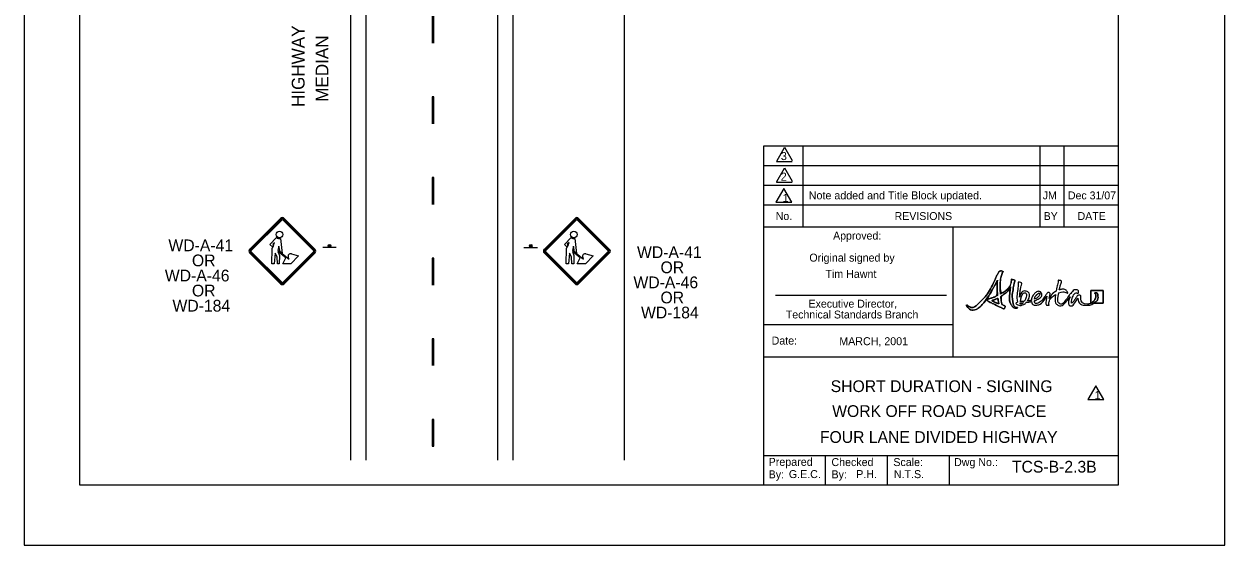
# Model space of a CAD drawing. Extents: x 1351 to 1567, y 178 to 457.
# Drawn here: x 1351.4 to 1567.4, y 177.9 to 271.7 of the extents above; entities that cross this region are included whole.
import ezdxf

# ---------------------------------------------------------------- set-up
doc = ezdxf.new("R2010")
doc.units = 0
for name, color, linetype in [('Level 1', 7, 'Continuous'), ('Level 10', 7, 'Continuous'), ('Level 2', 7, 'Continuous'), ('Level 22', 7, 'Continuous'), ('Level 44', 7, 'Continuous'), ('Level 45', 7, 'Continuous'), ('Level 53', 7, 'Continuous'), ('Level 60', 7, 'Continuous'), ('Level 63', 7, 'Continuous'), ('Level 7', 7, 'Continuous')]:
    doc.layers.add(name, color=color, linetype=linetype)

# ---------------------------------------------------------------- blocks, each defined once
blk = doc.blocks.new('ORIG')
at = {"layer": 'Level 2'}
blk.add_line((0, 0), (0, 0), dxfattribs=at)
at = {"layer": 'Level 7'}
for s, p in [('Original signed by', (-25.835, -6.257)), ('Tim Hawnt', (-22.945, -9.191))]:
    blk.add_text(s, height=1.434, dxfattribs=at).set_placement(p)
blk = doc.blocks.new('REVBK')
at = {"layer": 'Level 44'}
for p, q in [((63.873, 14.55), (-0.007, 14.55)), ((63.873, 11.001), (-0.007, 11.001)), ((63.873, 7.452), (-0.007, 7.452)), ((63.873, 3.904), (-0.007, 3.904)), ((0, 0), (63.873, 0))]:
    blk.add_line(p, q, dxfattribs=at)
blk.add_lwpolyline([(3.62, 6.885), (2.201, 4.415), (5.039, 4.415)], close=True, dxfattribs=at)
at = {"layer": 'Level 45'}
blk.add_line((34.066, 0), (34.066, 0), dxfattribs=at)
at = {"layer": 'Level 63'}
for p, q in [((0, 8.078), (0, 14.55)), ((7.09, 8.078), (7.09, 14.55)), ((49.679, 14.55), (49.679, 0)), ((53.99, 14.55), (53.99, 0)), ((0, 0), (0, 8.078)), ((7.09, 0), (7.09, 8.078))]:
    blk.add_line(p, q, dxfattribs=at)
for points in [[(3.699, 14.219), (2.306, 11.794)], [(5.181, 11.871), (3.787, 14.296)], [(2.306, 11.794), (2.28, 11.749), (5.119, 11.749), (5.093, 11.794)], [(3.699, 10.503), (2.306, 8.078)], [(5.181, 8.155), (3.787, 10.58)], [(2.306, 8.078), (2.28, 8.033), (5.119, 8.033), (5.093, 8.078)]]:
    blk.add_lwpolyline(points, dxfattribs=at)
at = {"layer": 'Level 44'}
for s, height, p in [('3', 1.448, (3.089, 12.018)), ('2', 1.448, (3.072, 8.302)), ('1', 1.448, (3.393, 4.472)), ('JM', 1.4189, (50.183, 4.953)), ('Dec 31/07', 1.419, (54.724, 4.953)), ('No.', 1.4195, (2.172, 1.235)), ('REVISIONS', 1.4195, (23.555, 1.235)), ('BY', 1.4194, (50.361, 1.235)), ('DATE', 1.4194, (56.463, 1.235))]:
    blk.add_text(s, height=height, rotation=360, dxfattribs=at).set_placement(p)
blk = doc.blocks.new('C_LINE')
at = {"layer": 'Level 2'}
for p, q in [((-0.145, 77.408), (-0.145, 72.57)), ((0.145, 72.57), (0.145, 77.408)), ((-0.145, 62.894), (-0.145, 58.056)), ((0.145, 62.894), (-0.145, 62.894)), ((0.145, 58.056), (0.145, 62.894)), ((-0.145, 48.38), (-0.145, 43.542)), ((0.145, 48.38), (-0.145, 48.38)), ((0.145, 43.542), (0.145, 48.38)), ((-0.145, 33.866), (-0.145, 29.028)), ((0.145, 33.866), (-0.145, 33.866)), ((0.145, 29.028), (0.145, 33.866)), ((-0.145, 19.352), (-0.145, 14.514)), ((0.145, 19.352), (-0.145, 19.352)), ((0.145, 14.514), (0.145, 19.352)), ((-0.145, 4.838), (-0.145, 0)), ((0.145, 4.838), (-0.145, 4.838)), ((0.145, 0), (0.145, 4.838)), ((-0.145, 0), (0.145, 0))]:
    blk.add_line(p, q, dxfattribs=at)
blk = doc.blocks.new('Alberta Signature')
at = {"layer": 'Level 53'}
blk.add_line((-5.9, -14.5), (-13.3, -14.5), dxfattribs=at)
blk.add_lwpolyline([(-5.9, -14.5), (15.6, -14.5), (15.6, 15.2), (-14.1, 15.2), (-14.1, -14.5), (-13.3, -14.5)], dxfattribs=at)
for points, degree in [([(-192.4, -25.3), (-195.6, -24.8), (-199.8, -20.5), (-201, -13.3), (-203.3, -0.4), (-202, 12.3), (-198.2, 31.2), (-197.5, 34.8), (-195, 41), (-202.8, 42.2), (-205.3, 42.6), (-204, 41.4), (-204.7, 38.1), (-207.7, 24), (-219.2, 13.8), (-230.8, 7), (-232, 23.2), (-231.5, 41.1), (-228.5, 52.1), (-225.9, 61.4), (-222.9, 59.7), (-226.7, 61.7), (-230.6, 63.7), (-234.9, 61), (-238.4, 54.1), (-241.8, 47.2), (-257.8, 9.6), (-283.3, -15.7), (-296.3, -28.7), (-308.1, -22), (-310.5, -20), (-312.4, -18.4), (-313.1, -20.9), (-310.7, -23.5), (-300.2, -34.8), (-284.8, -28.3), (-279.2, -22.7), (-263.7, -7.2), (-245.6, 26.2), (-238.3, 40.3), (-239, 32.3), (-239.2, 19), (-237.8, 3.3), (-245.7, -0.5), (-252.7, -2.8), (-256.1, -3.7), (-259.7, -4.6), (-261.9, -6.1), (-262, -7.8), (-262.1, -9.6), (-259.6, -11.2), (-256.1, -12.8), (-249.9, -15.8), (-231.6, -24.4), (-227.1, -27), (-223.2, -29.3), (-221.3, -27.5), (-220.2, -25.1), (-218.7, -22), (-222.8, -20.2), (-226.8, -19), (-228.3, -13.7), (-229.5, -6.5), (-230.3, 1.3), (-221, 7.1), (-211.9, 14.7), (-206.6, 24.2), (-207.9, 16.3), (-211.3, -10.8), (-202.8, -22.3), (-200.9, -24.8), (-196.7, -27.5), (-192.7, -27.1), (-190.8, -26.9), (-189.8, -25.7), (-190, -25.3), (-190.2, -24.9), (-191.3, -25.5), (-192.4, -25.3)], 3), ([(-230.8, 7), (-232, 23.2), (-231.5, 41.1), (-228.5, 52.1), (-225.9, 61.4), (-222.9, 59.7), (-226.7, 61.7), (-230.6, 63.7), (-234.9, 61), (-238.4, 54.1), (-241.8, 47.2), (-257.8, 9.6), (-283.3, -15.7), (-296.3, -28.7), (-308.1, -22), (-310.5, -20), (-312.4, -18.4), (-313.1, -20.9), (-310.7, -23.5), (-300.2, -34.8), (-284.8, -28.3), (-279.2, -22.7), (-263.7, -7.2), (-245.6, 26.2), (-238.3, 40.3)], 3), ([(-238.3, 40.3), (-239, 32.3), (-239.2, 19), (-237.8, 3.3)], 2), ([(-192.4, -25.3), (-195.6, -24.8), (-199.8, -20.5), (-201, -13.3), (-203.3, -0.4), (-202, 12.3), (-198.2, 31.2), (-197.5, 34.8), (-195, 41), (-202.8, 42.2), (-205.3, 42.6), (-204, 41.4), (-204.7, 38.1), (-207.7, 24), (-219.2, 13.8), (-230.8, 7)], 3), ([(-185.2, -0.7), (-184.6, 6.9), (-183.4, 16.1), (-181.7, 24.7), (-181, 28.2), (-178.5, 34.4), (-186.3, 35.6), (-188.8, 36), (-188.4, 34.9), (-188.2, 31.5), (-187.9, 27), (-192.9, -0.2), (-190.3, -12.1)], 3), ([(-89.8, 17.1), (-89, 21.1), (-88, 25.1), (-86.9, 29.1), (-85.9, 32.6), (-82.9, 38.9), (-90.6, 40), (-93.1, 40.4), (-92, 39.2), (-92.8, 35.9), (-94.3, 29.8), (-96.2, 21.9), (-97.5, 14)], 3), ([(-237.8, 3.3), (-245.7, -0.5), (-252.7, -2.8), (-256.1, -3.7), (-259.7, -4.6), (-261.9, -6.1), (-262, -7.8), (-262.1, -9.6), (-259.6, -11.2), (-256.1, -12.8), (-249.9, -15.8), (-231.6, -24.4), (-227.1, -27), (-223.2, -29.3), (-221.3, -27.5), (-220.2, -25.1), (-218.7, -22), (-222.8, -20.2), (-226.8, -19)], 3), ([(-230.3, 1.3), (-221, 7.1), (-211.9, 14.7), (-206.6, 24.2)], 2), ([(-226.8, -19), (-228.3, -13.7), (-229.5, -6.5), (-230.3, 1.3)], 2), ([(-206.6, 24.2), (-207.9, 16.3), (-211.3, -10.8), (-202.8, -22.3), (-200.9, -24.8), (-196.7, -27.5), (-192.7, -27.1), (-190.8, -26.9), (-189.8, -25.7), (-190, -25.3), (-190.2, -24.9), (-191.3, -25.5), (-192.4, -25.3)], 3), ([(-166.1, -9.6), (-160.5, -0.6), (-161, 11.5), (-169.1, 13.6), (-178.5, 16), (-183.2, 6.8), (-185.2, -0.7)], 3), ([(-183.2, -11.3), (-182, -1.7), (-177, 11.5), (-170.8, 9.4), (-167.3, 8.2), (-169.1, -3), (-173.7, -10.4)], 3), ([(-149.7, -9.2), (-148.4, -8.9), (-147.3, -8.5), (-146.3, -8), (-134.5, -2.8), (-130.5, 5.1), (-133.5, 9.9), (-136.3, 14.4), (-144.5, 13), (-150.9, 6.3), (-154, 2.9), (-156.5, -2.8), (-156.7, -8)], 3), ([(-156.6, -10.9), (-156, -16.2), (-152.6, -20.2), (-144.6, -19.4), (-133.4, -18.4), (-123.3, -4.5), (-119.6, 2.2)], 3), ([(-114.1, -3.7), (-113.3, 0), (-112.2, 4), (-112.1, 6.8), (-112, 9.7), (-114, 10.3), (-114.8, 10.6), (-116.4, 11), (-118.5, 10.2), (-120.5, 7.4), (-125.2, 0.7), (-131.2, -9.8), (-140.2, -14.2), (-146.7, -17.3), (-149.6, -14.1), (-149.7, -9.2)], 3), ([(-143.4, 5.7), (-139.5, 9.3), (-137.5, 9.1), (-137, 8.1), (-135.9, 6), (-140.5, -1.5), (-149.4, -5.6)], 3), ([(-149.4, -5.6), (-148.7, -1.6), (-146.5, 2.8), (-143.4, 5.7)], 2), ([(-119.6, 2.2), (-120.2, -5), (-124.9, -20.6), (-117, -19.8), (-113.8, -19.5), (-115.2, -19), (-115, -16.3), (-114.3, -6.9), (-106.5, 1.1), (-98.7, 6)], 3), ([(-97.5, 14), (-103.9, 10.4), (-109.7, 4.3), (-114.1, -3.7)], 2), ([(-98.7, 6), (-100.1, -5.6), (-99.6, -15.9), (-94.4, -19.1), (-84.7, -25.2), (-71.1, -9.3), (-63.6, 0.4)], 3), ([(-22.5, -17.1), (-34.7, -17.1), (-37.8, -7.7), (-38.4, -3), (-38.8, 0.2), (-38.1, 4.7), (-43.5, 4.1), (-47.3, 3.7), (-50.7, -3.7), (-55.5, -9.9), (-59.6, -15.2), (-61.4, -14.7), (-60.5, -10.1), (-59.3, -4.4), (-54.5, 9), (-49.1, 10), (-46.5, 10.4), (-45.6, 6), (-44.5, 8.8), (-43.3, 11.5), (-44.4, 17.5), (-50, 17.5), (-54, 17.5), (-58.7, 13.3), (-62.6, 8.6), (-66, 4.4), (-83.1, -20.8), (-90.3, -15.4), (-93.7, -12.8), (-93.4, -2.5), (-91.3, 9.8)], 3), ([(-91.3, 9.8), (-82.8, 13), (-75.7, 12), (-71.7, 10), (-69.7, 9.1), (-69.4, 9.2), (-70.3, 11.4), (-71.5, 14.6), (-78.4, 19.6), (-89.1, 17.3), (-89.3, 17.3), (-89.6, 17.2), (-89.8, 17.1)], 3), ([(-63.6, 0.4), (-67.4, -8.2), (-69.6, -19.3), (-63.8, -20.9), (-57.1, -22.9), (-51.8, -11.7), (-45.6, -3.2)], 3), ([(-14.1, 15.2), (-14.1, 15.2), (-14.1, -14.5), (-14.1, -14.5), (-14.1, -14.5), (-13.3, -14.5), (-13.3, -14.5), (-6.8, -10.6), (-2.5, -3.2), (-2.5, 2.8), (-2.5, 8.1), (-5.3, 7.8), (-4.9, 8.6), (-4, 10.7), (2.5, 9.5), (2.9, 2), (3.2, -4.2), (-0.1, -10.3), (-5.9, -14.5), (-5.9, -14.5), (15.6, -14.5), (15.6, -14.5), (15.6, -14.5), (15.6, 15.2), (15.6, 15.2), (15.6, 15.2), (-14.1, 15.2), (-14.1, 15.2)], 3), ([(-13.3, -14.5), (-6.8, -10.6), (-2.5, -3.2), (-2.5, 2.8), (-2.5, 8.1), (-5.3, 7.8), (-4.9, 8.6), (-4, 10.7), (2.5, 9.5), (2.9, 2), (3.2, -4.2), (-0.1, -10.3), (-5.9, -14.5)], 3), ([(-252, -9.1), (-247.9, -7.6), (-242.7, -5.4), (-237.1, -2.5)], 2), ([(-252, -9.1), (-247.9, -7.6), (-242.7, -5.4), (-237.1, -2.5), (-236.4, -8.8), (-235.6, -13.4), (-234.7, -16.8), (-238.7, -15.3), (-244.5, -13), (-252, -9.1)], 3), ([(-234.7, -16.8), (-238.7, -15.3), (-244.5, -13), (-252, -9.1)], 2), ([(-237.1, -2.5), (-236.4, -8.8), (-235.6, -13.4), (-234.7, -16.8)], 2), ([(-190.3, -12.1), (-193.6, -13.2), (-195, -15.7), (-190.7, -18.4), (-187.7, -20.2), (-181.2, -20.8), (-174.6, -17.5), (-172.2, -16.4), (-170.2, -14.7), (-168.5, -12.8)], 3), ([(-184.2, -17), (-183.8, -16.7), (-183.5, -16.1), (-183.5, -15.5), (-183.5, -15.1), (-183.5, -14.7), (-183.5, -14.2)], 3), ([(-181.5, -17), (-182.6, -17.2), (-183.5, -17.2), (-184.2, -17)], 2), ([(-183.5, -14.2), (-181.8, -14.2), (-179.2, -14), (-176.1, -13.7)], 2), ([(-173.7, -10.4), (-176.7, -10.7), (-179.9, -11), (-183.2, -11.3)], 2), ([(-176.1, -13.7), (-177.7, -15.5), (-179.6, -16.7), (-181.5, -17)], 2), ([(-168.5, -12.8), (-164.5, -12.3), (-160.4, -11.7), (-156.6, -10.9)], 2), ([(-156.7, -8), (-159.5, -8.6), (-162.6, -9.1), (-166.1, -9.6)], 2), ([(-45.6, -3.2), (-44.9, -9.3), (-40.8, -19.9), (-24.3, -19.9), (-16.9, -19.9), (-10.6, -17.8), (-5.9, -14.5)], 3), ([(-13.3, -14.5), (-16, -16.1), (-19.1, -17.1), (-22.5, -17.1)], 2)]:
    blk.add_open_spline(points, degree=degree, dxfattribs=at)

msp = doc.modelspace()

# ---------------------------------------------------------------- linework, layer by layer
at = {"layer": 'Level 1'}
for p, q in [((1397.56, 236.71), (1391.99, 231.14)), ((1397.69, 236.59), (1392.11, 231.02)), ((1397.81, 236.47), (1392.23, 230.89)), ((1403.52, 230.89), (1397.94, 236.47)), ((1403.64, 231.02), (1398.07, 236.59)), ((1403.77, 231.14), (1398.19, 236.71)), ((1450.53, 236.71), (1444.95, 231.14)), ((1450.65, 236.59), (1445.07, 231.02)), ((1450.78, 236.47), (1445.2, 230.89)), ((1456.49, 230.89), (1450.91, 236.47)), ((1456.61, 231.02), (1451.03, 236.59)), ((1456.73, 231.14), (1451.16, 236.71)), ((1397.62, 234.27), (1397.6, 234.27)), ((1450.58, 234.27), (1450.57, 234.27)), ((1484.44, 188.73), (1484.44, 235.19)), ((1518.49, 235.19), (1518.49, 211.79)), ((1391.98, 230.51), (1397.56, 224.94)), ((1392.11, 230.64), (1397.68, 225.06)), ((1392.23, 230.76), (1397.81, 225.19)), ((1397.94, 225.19), (1403.52, 230.76)), ((1398.07, 225.06), (1403.64, 230.63)), ((1398.19, 224.94), (1403.77, 230.51)), ((1444.95, 230.51), (1450.52, 224.94)), ((1445.07, 230.64), (1450.65, 225.06)), ((1445.2, 230.76), (1450.77, 225.19)), ((1450.91, 225.19), (1456.48, 230.76)), ((1451.03, 225.06), (1456.61, 230.63)), ((1451.15, 224.94), (1456.73, 230.51)), ((1484.44, 217.64), (1518.49, 217.64)), ((1484.44, 211.79), (1548.28, 211.79)), ((1484.44, 194.05), (1548.28, 194.05)), ((1495.57, 188.73), (1495.57, 194.05)), ((1506.7, 188.73), (1506.7, 194.05)), ((1517.83, 194.05), (1517.83, 188.73))]:
    msp.add_line(p, q, dxfattribs=at)
for points in [[(1396.15, 232.06), (1396.29, 231.95), (1396.13, 231.55), (1395.62, 232.03), (1396.84, 233.28)], [(1396.15, 232.06), (1396.29, 231.95), (1396.13, 231.55), (1395.62, 232.03), (1396.84, 233.28)], [(1396.57, 230.46), (1396.39, 228.55), (1395.97, 228.55), (1396.03, 231.28), (1396.13, 231.55), (1395.62, 232.03), (1396.84, 233.28)], [(1449.12, 232.06), (1449.26, 231.95), (1449.1, 231.55), (1448.59, 232.03), (1449.81, 233.28)], [(1449.12, 232.06), (1449.26, 231.95), (1449.1, 231.55), (1448.59, 232.03), (1449.81, 233.28)], [(1449.54, 230.46), (1449.36, 228.55), (1448.93, 228.55), (1448.99, 231.28), (1449.1, 231.55), (1448.59, 232.03), (1449.81, 233.28)], [(1399.51, 230.33), (1400.79, 229.95), (1399.41, 228.55), (1397.95, 228.55), (1398.5, 229.61), (1397.08, 230.77), (1397.36, 230.03), (1397.32, 228.55), (1396.98, 228.55), (1396.91, 229.81), (1396.57, 230.46), (1396.39, 228.55), (1395.97, 228.55), (1396.03, 231.28), (1396.46, 232.38), (1396.15, 232.06)], [(1399.51, 230.33), (1400.79, 229.95), (1399.41, 228.55), (1397.95, 228.55), (1398.5, 229.61), (1397.08, 230.77), (1397.36, 230.03), (1397.32, 228.55), (1396.98, 228.55), (1396.91, 229.81), (1396.57, 230.46), (1396.39, 228.55), (1395.97, 228.55), (1396.03, 231.28), (1396.46, 232.38), (1396.15, 232.06)], [(1397.54, 233.1), (1397.82, 230.38), (1397.46, 230.68), (1397.25, 231.7), (1397.08, 230.99), (1399.07, 229.35), (1398.93, 229.71)], [(1397.54, 233.1), (1397.82, 230.38), (1397.46, 230.68), (1397.25, 231.7), (1397.08, 230.99), (1399.07, 229.35), (1398.93, 229.71)], [(1397.54, 233.1), (1397.82, 230.38), (1399.07, 229.35), (1398.93, 229.71)], [(1452.48, 230.33), (1453.76, 229.95), (1452.37, 228.55), (1450.91, 228.55), (1451.46, 229.61), (1450.05, 230.77), (1450.32, 230.03), (1450.29, 228.55), (1449.94, 228.55), (1449.88, 229.81), (1449.54, 230.46), (1449.36, 228.55), (1448.93, 228.55), (1448.99, 231.28), (1449.43, 232.38), (1449.12, 232.06)], [(1452.48, 230.33), (1453.76, 229.95), (1452.37, 228.55), (1450.91, 228.55), (1451.46, 229.61), (1450.05, 230.77), (1450.32, 230.03), (1450.29, 228.55), (1449.94, 228.55), (1449.88, 229.81), (1449.54, 230.46), (1449.36, 228.55), (1448.93, 228.55), (1448.99, 231.28), (1449.43, 232.38), (1449.12, 232.06)], [(1450.5, 233.1), (1450.79, 230.38), (1450.42, 230.68), (1450.22, 231.7), (1450.05, 230.99), (1452.03, 229.35), (1451.9, 229.71)], [(1450.5, 233.1), (1450.79, 230.38), (1450.42, 230.68), (1450.22, 231.7), (1450.05, 230.99), (1452.03, 229.35), (1451.9, 229.71)], [(1450.5, 233.1), (1450.79, 230.38), (1452.03, 229.35), (1451.9, 229.71)], [(1399.51, 230.33), (1400.79, 229.95), (1399.41, 228.55), (1397.95, 228.55), (1398.5, 229.61), (1397.08, 230.77), (1397.36, 230.03), (1397.32, 228.55), (1396.98, 228.55), (1396.91, 229.81), (1396.57, 230.46)], [(1452.48, 230.33), (1453.76, 229.95), (1452.37, 228.55), (1450.91, 228.55), (1451.46, 229.61), (1450.05, 230.77), (1450.32, 230.03), (1450.29, 228.55), (1449.94, 228.55), (1449.88, 229.81), (1449.54, 230.46)]]:
    msp.add_lwpolyline(points, dxfattribs=at)
for points in [[(1396.15, 232.06), (1396.29, 231.95), (1396.46, 232.38)], [(1397.46, 230.68), (1397.25, 231.7), (1397.08, 230.99)], [(1449.12, 232.06), (1449.26, 231.95), (1449.43, 232.38)], [(1450.42, 230.68), (1450.22, 231.7), (1450.05, 230.99)], [(1544.18, 206.59), (1542.77, 204.12), (1545.6, 204.12)]]:
    msp.add_lwpolyline(points, close=True, dxfattribs=at)
for centre in [(1397.35, 233.81), (1397.35, 233.81), (1397.35, 233.81), (1450.31, 233.81), (1450.31, 233.81), (1450.31, 233.81)]:
    msp.add_circle(centre, 0.591, dxfattribs=at)
for centre, radius, start, end in [((1397.88, 236.4), 0.446, 45, 134.9651), ((1397.88, 236.4), 0.27, 45, 134.9651), ((1397.88, 236.4), 0.0948, 45, 134.9651), ((1450.84, 236.4), 0.446, 45, 134.9651), ((1450.84, 236.4), 0.27, 45, 134.9651), ((1450.84, 236.4), 0.0948, 45, 134.9651), ((1397.35, 233.81), 0.734, 226.3135, 284.9576), ((1397.35, 233.81), 0.734, 226.3135, 284.9576), ((1397.35, 233.81), 0.734, 226.3135, 284.9576), ((1450.31, 233.81), 0.734, 226.3135, 284.9576), ((1450.31, 233.81), 0.734, 226.3135, 284.9576), ((1450.31, 233.81), 0.734, 226.3135, 284.9576), ((1392.3, 230.83), 0.446, 134.965, 225), ((1403.45, 230.82), 0.446, 314.9651, 45), ((1445.27, 230.83), 0.446, 134.965, 225), ((1456.42, 230.82), 0.446, 314.9651, 45), ((1392.3, 230.83), 0.27, 134.965, 225), ((1392.3, 230.83), 0.0948, 134.965, 225), ((1399.37, 229.88), 0.475, 73.381, 201.0999), ((1399.37, 229.88), 0.475, 73.381, 201.0999), ((1399.37, 229.88), 0.475, 73.381, 201.0999), ((1403.45, 230.82), 0.0948, 314.9651, 45), ((1403.45, 230.82), 0.27, 314.9651, 45), ((1445.27, 230.83), 0.27, 134.965, 225), ((1445.27, 230.83), 0.0948, 134.965, 225), ((1452.34, 229.88), 0.475, 73.381, 201.0999), ((1452.34, 229.88), 0.475, 73.381, 201.0999), ((1452.34, 229.88), 0.475, 73.381, 201.0999), ((1456.42, 230.82), 0.0948, 314.9651, 45), ((1456.42, 230.82), 0.27, 314.9651, 45), ((1397.87, 225.25), 0.446, 225, 314.9652), ((1397.87, 225.25), 0.27, 225, 314.9652), ((1397.87, 225.25), 0.0948, 225, 314.9652), ((1450.84, 225.25), 0.446, 225, 314.9652), ((1450.84, 225.25), 0.27, 225, 314.9652), ((1450.84, 225.25), 0.0948, 225, 314.9652)]:
    msp.add_arc(centre, radius, start, end, dxfattribs=at)
at = {"layer": 'Level 10'}
for p, q in [((1410.15, 439.12), (1410.15, 193.22)), ((1412.88, 439.12), (1412.88, 193.22)), ((1436.58, 439.12), (1436.58, 193.22)), ((1439.33, 439.12), (1439.33, 193.22)), ((1459.33, 437.79), (1459.33, 193.22)), ((1548.28, 188.73), (1548.28, 188.73)), ((1548.28, 188.73), (1548.28, 188.73))]:
    msp.add_line(p, q, dxfattribs=at)
at = {"layer": 'Level 22'}
msp.add_line((1499.9, 188.73), (1499.9, 188.73), dxfattribs=at)
at = {"layer": 'Level 44'}
for p, q in [((1407.56, 231.49), (1405.14, 231.49)), ((1441.33, 231.49), (1443.75, 231.49))]:
    msp.add_line(p, q, dxfattribs=at)
for centre, radius in [((1406.34, 231.76), 0.242), ((1406.34, 231.76), 0.121), ((1442.54, 231.76), 0.242), ((1442.54, 231.76), 0.121)]:
    msp.add_circle(centre, radius, dxfattribs=at)
at = {"layer": 'Level 60'}
for p, q in [((1361.41, 188.73), (1361.41, 188.73)), ((1351.41, 177.92), (1351.41, 177.92))]:
    msp.add_line(p, q, dxfattribs=at)
for points in [[(1567.41, 456.92), (1351.41, 456.92), (1351.41, 177.92), (1567.41, 177.92)], [(1548.28, 446.11), (1361.41, 446.11), (1361.41, 188.73), (1548.28, 188.73)]]:
    msp.add_lwpolyline(points, close=True, dxfattribs=at)
at = {"layer": 'Level 7'}
msp.add_line((1486.55, 222.88), (1517.35, 222.88), dxfattribs=at)

# ---------------------------------------------------------------- block references
at = {"layer": 'Level 2'}
for name, p in [('C_LINE', (1424.96, 195.69)), ('ORIG', (1518.49, 235.19))]:
    msp.add_blockref(name, p, dxfattribs=at)
at = {"layer": 'Level 44'}
msp.add_blockref('REVBK', (1484.44, 235.19), dxfattribs=at)
at = {"layer": 'Level 60', "xscale": 0.075, "yscale": 0.075}
msp.add_blockref('Alberta Signature', (1544.35, 222.57), dxfattribs=at)

# ---------------------------------------------------------------- texts
at = {"layer": 'Level 1'}
for s, height, p in [('Note added and Title Block updated.', 1.44, (1492.55, 240.14)), ('Date:', 1.433, (1485.87, 214)), ('1', 1.45, (1543.96, 204.18)), ('Prepared', 1.44, (1485.33, 192.17)), ('Checked', 1.433, (1496.63, 192.13)), ('Scale:', 1.433, (1507.76, 192.13)), ('Dwg No.:', 1.433, (1518.68, 192.13)), ('By:', 1.44, (1485.33, 189.92)), ('By:', 1.44, (1496.63, 189.92)), ('    N.T.S.   ', 1.4329, (1505.73, 189.96))]:
    msp.add_text(s, height=height, rotation=360, dxfattribs=at).set_placement(p)
at = {"layer": 'Level 10'}
for s, height, rotation, p in [('HIGHWAY', 2.298, 90, (1401.87, 256.76)), ('MEDIAN', 2.298, 90, (1406.16, 257.7)), ('WD-A-41', 2.115, 0, (1377.38, 230.8)), ('WD-A-41', 2.115, 360, (1461.66, 229.57)), ('OR', 2.115, 0, (1381.61, 228.09)), ('OR', 2.115, 360, (1465.89, 226.85)), ('WD-A-46', 2.115, 0, (1376.74, 225.37)), ('OR', 2.115, 0, (1381.61, 222.66)), ('WD-A-46', 2.115, 360, (1461.02, 224.14)), ('OR', 2.115, 360, (1465.88, 221.42)), ('WD-184', 2.115, 0, (1378.11, 219.94)), ('WD-184', 2.115, 360, (1462.38, 218.71)), ('SHORT DURATION - SIGNING', 2.115, 360, (1496.49, 205.45)), ('WORK OFF ROAD SURFACE', 2.115, 360, (1496.76, 200.97)), ('FOUR LANE DIVIDED HIGHWAY', 2.1152, 360, (1494.55, 196.3))]:
    msp.add_text(s, height=height, rotation=rotation, dxfattribs=at).set_placement(p)
at = {"layer": 'Level 60'}
for s, height, p in [('MARCH, 2001', 1.434, (1498.04, 213.89)), ('TCS-B-2.3B', 2.115, (1529.09, 190.96))]:
    msp.add_text(s, height=height, dxfattribs=at).set_placement(p)
for s, p in [('G.E.C.', (1488.97, 189.97)), ('P.H.', (1501.09, 189.97))]:
    msp.add_text(s, height=1.433, rotation=360, dxfattribs=at).set_placement(p)
at = {"layer": 'Level 7'}
for s, height, p in [('Approved:', 1.419, (1496.93, 232.9)), ('Executive Director,', 1.4187, (1492.52, 220.65)), ('Technical Standards Branch', 1.4187, (1488.43, 218.7))]:
    msp.add_text(s, height=height, dxfattribs=at).set_placement(p)

doc.saveas('drawing.dxf')
